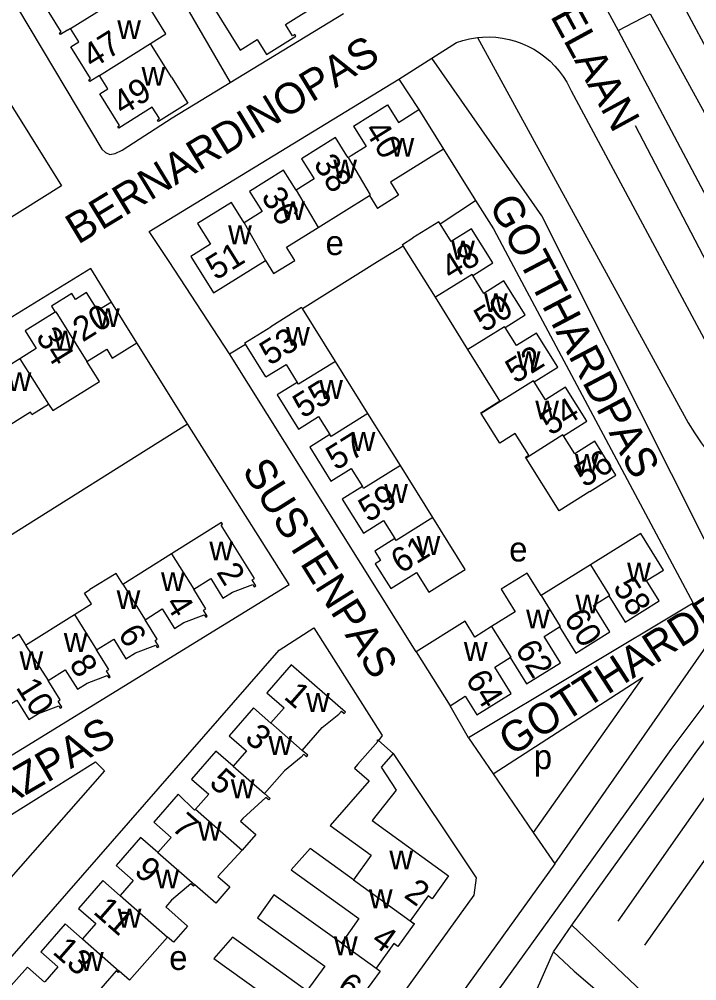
# Model space of a CAD drawing. Extents: x 158848 to 160613, y 385889 to 387762.
# Drawn here: x 159208.8 to 159319.2, y 386865.6 to 387022.2 of the extents above; entities that cross this region are included whole.
import ezdxf

# ---------------------------------------------------------------- set-up
doc = ezdxf.new("R2010")
doc.units = 0
for name, color, linetype in [('BLT_Basislijn', 7, 'Continuous'), ('BLT_Bebouwing', 7, 'Continuous'), ('BLT_Centroide', 7, 'Continuous'), ('BLT_Huisnummer', 7, 'Continuous'), ('BLT_Huisnummer_ tussenligend', 7, 'Continuous'), ('BLT_Onderverdeling_panden', 7, 'Continuous'), ('BLT_Straatnaam', 7, 'Continuous')]:
    doc.layers.add(name, color=color, linetype=linetype)

msp = doc.modelspace()

# ---------------------------------------------------------------- linework, layer by layer
at = {"layer": 'BLT_Basislijn'}
for p, q in [((159169.08, 387139.45), (159243.17, 387011.94)), ((159332.92, 386994.75), (159255.77, 387139.62)), ((159303.99, 387024.92), (159306.4, 387020.4)), ((159243.17, 387011.94), (159261.66, 387023.2)), ((159306.4, 387020.4), (159321.81, 386991.43)), ((159276.05, 387015.9), (159280.06, 387018.45)), ((159283.47, 387019.26), (159317.82, 386956.49)), ((159270.65, 387012.47), (159276.05, 387015.9)), ((159230, 386987.67), (159270.65, 387012.47)), ((159270.65, 387012.47), (159273.93, 387007.51)), ((159298.76, 387010.57), (159327.13, 386957.61)), ((159309.19, 387004.92), (159331.36, 386962.4)), ((159277.97, 387001.09), (159283.15, 386992.73)), ((159277.42, 386988.9), (159283.15, 386992.73)), ((159233.22, 386982.75), (159230, 386987.67)), ((159267.17, 386982.75), (159271.36, 386985.34)), ((159243.08, 386967.71), (159233.22, 386982.75)), ((159254.94, 386975.12), (159267.17, 386982.75)), ((159223.81, 386976.15), (159220.45, 386981.6)), ((159236.2, 386956.34), (159227.95, 386969.49)), ((159243.08, 386967.71), (159245.65, 386969.32)), ((159273.52, 386919.16), (159243.08, 386967.71)), ((159160.9, 386909.02), (159236.2, 386956.34)), ((159296.07, 386884.6), (159325.68, 386927.08)), ((159286.03, 386899.29), (159310.46, 386915.04)), ((159310.46, 386915.04), (159292.57, 386889.73)), ((159306.42, 386875.27), (159333.13, 386913.44)), ((159282.03, 386905.15), (159279.02, 386910.38)), ((159282.03, 386905.15), (159286.03, 386899.29)), ((159286.03, 386899.29), (159292.57, 386889.73)), ((159292.57, 386889.73), (159296.07, 386884.6)), ((159296.07, 386884.6), (159293.14, 386880.53)), ((159293.14, 386880.53), (159270.22, 386848.72)), ((159295.86, 386870.3), (159298.87, 386874.61)), ((159299.26, 386867.13), (159295.86, 386870.3))]:
    msp.add_line(p, q, dxfattribs=at)
for points in [[(159145.06, 387124.74), (159208.51, 387024.1), (159222.28, 387001.08), (159222.83, 387000.51), (159223.59, 387000.22), (159224.44, 387000.38), (159225.59, 387000.9), (159233.73, 387006.19), (159243.17, 387011.94)], [(159195.05, 387028.15), (159215.7, 386995.08), (159195.96, 386982.75)], [(159306.4, 387020.4), (159311.62, 387023.13), (159339.73, 386971.98)], [(159280.06, 387018.45), (159281.1, 387018.79), (159282.16, 387019.05), (159283.47, 387019.26)], [(159283.47, 387019.26), (159284.32, 387019.34), (159285.41, 387019.36), (159286.5, 387019.31), (159287.58, 387019.17), (159288.65, 387018.96), (159289.7, 387018.67), (159290.73, 387018.3), (159291.72, 387017.86), (159292.68, 387017.34), (159293.6, 387016.76), (159294.48, 387016.11), (159295.31, 387015.4), (159296.08, 387014.62), (159296.79, 387013.8), (159297.44, 387012.92), (159298.03, 387012), (159298.76, 387010.57)], [(159325.68, 386927.08), (159293.98, 386990.2), (159276.05, 387015.9)], [(159283.15, 386992.73), (159286.1, 386988.08), (159288.94, 386982.75)], [(159288.94, 386982.75), (159318.62, 386927.1), (159282.03, 386905.15)], [(159220.45, 386981.6), (159144.84, 386935.16), (159160.9, 386909.02)], [(159176.65, 386883.38), (159252.82, 386930.16), (159236.2, 386956.34)], [(159317.82, 386956.49), (159318.84, 386954.84), (159319.93, 386953.24), (159321.08, 386951.68), (159322.3, 386950.18), (159323.58, 386948.72), (159324.92, 386947.32), (159326.32, 386945.97), (159327.76, 386944.68), (159329.27, 386943.46), (159330.82, 386942.29), (159332.41, 386941.19), (159333.9, 386940.26)], [(159298.87, 386874.61), (159318.95, 386902.62), (159324.3, 386909.78), (159335.81, 386922.28), (159348.89, 386933.11)], [(159194.56, 386854.66), (159251.14, 386919.42), (159256.83, 386923.09), (159267.95, 386905.52), (159267.38, 386904.72)], [(159296.26, 386877.04), (159309.87, 386896.01), (159315.07, 386903.25), (159322.05, 386912.59), (159324, 386914.92)], [(159269.77, 386902.62), (159283.29, 386882.36), (159282.88, 386879.51), (159247.88, 386831.04), (159239.74, 386817.6), (159233.63, 386805.78), (159231.19, 386803.34), (159228.75, 386802.93), (159225.9, 386804.56), (159224.01, 386807.98)], [(159181.14, 386876.17), (159221.23, 386901.24), (159222.71, 386899.76), (159189.75, 386862.37)], [(159310.74, 386871.38), (159328.79, 386896.94), (159324.05, 386900.29)], [(159232.18, 386773.77), (159236.4, 386782.61), (159244.66, 386799.9), (159250.23, 386811.52), (159258.13, 386823.58), (159262.54, 386830.82), (159270.01, 386841.29), (159276.78, 386849.92), (159287.2, 386864.43), (159296.26, 386877.04)], [(159298.87, 386874.61), (159310.39, 386863.7), (159326.68, 386851.17), (159348.15, 386836.42)], [(159236.36, 386774.31), (159246.85, 386796.39), (159252.57, 386807.55), (159258.95, 386818.35), (159263.91, 386825.88), (159269.12, 386833.23), (159279.51, 386842.29), (159289.96, 386856.88), (159295.86, 386870.3)], [(159299.26, 386867.13), (159310.16, 386857.78)]]:
    msp.add_lwpolyline(points, dxfattribs=at)
at = {"layer": 'BLT_Bebouwing'}
for p, q in [((159217.13, 387020.74), (159216.66, 387020.45)), ((159217.14, 387020.71), (159217.13, 387020.74)), ((159233.63, 387012.81), (159230.2, 387018.29)), ((159262.41, 386999.69), (159262.22, 387000)), ((159262.9, 387000), (159262.41, 386999.69)), ((159257.54, 386988.32), (159265.88, 386993.52)), ((159265.88, 386993.52), (159267.2, 386991.41)), ((159276.62, 386976.93), (159271.36, 386985.34)), ((159281.94, 386968.43), (159276.62, 386976.93)), ((159260.32, 386966.5), (159254.94, 386975.12)), ((159249.01, 386963.95), (159245.65, 386969.32)), ((159265.62, 386958.02), (159260.32, 386966.5)), ((159210.86, 386957.84), (159213.57, 386959.52)), ((159270.92, 386949.54), (159265.62, 386958.02)), ((159276.22, 386941.06), (159270.92, 386949.54)), ((159233.63, 386935.12), (159225.68, 386930.16)), ((159301.91, 386933.34), (159293.85, 386928.32)), ((159225.68, 386930.16), (159225.67, 386930.18)), ((159289.65, 386925.69), (159285.79, 386923.29)), ((159209.84, 386920.26), (159217.8, 386925.25)), ((159209.83, 386920.29), (159209.84, 386920.26)), ((159273.52, 386919.16), (159279.02, 386910.38)), ((159249.82, 386907.59), (159249.8, 386907.56)), ((159267.25, 386904.84), (159267.38, 386904.72)), ((159267.38, 386904.72), (159269.77, 386902.62)), ((159243.68, 386900.55), (159243.65, 386900.52)), ((159231.39, 386886.49), (159231.37, 386886.46)), ((159225.25, 386879.45), (159225.23, 386879.43)), ((159272.53, 386875.35), (159273.18, 386874.89)), ((159273.18, 386874.89), (159273.15, 386874.84)), ((159219.1, 386872.42), (159219.08, 386872.39))]:
    msp.add_line(p, q, dxfattribs=at)
for points in [[(159243.66, 387027.03), (159242.84, 387026.52), (159243, 387026.25), (159240.22, 387024.51), (159244.79, 387017.2), (159247.57, 387018.94), (159249.1, 387016.49), (159253.86, 387019.47), (159253.7, 387019.74), (159253.36, 387019.53), (159252.21, 387021.39), (159257.66, 387024.79), (159257.49, 387025.06), (159257.21, 387024.89), (159253.99, 387030.04), (159252.65, 387029.22), (159251.29, 387031.43), (159253.44, 387032.76), (159253.27, 387033.03), (159252.99, 387032.86)], [(159216.66, 387020.45), (159215.52, 387019.74), (159215.36, 387020.02), (159215.63, 387020.19), (159212.4, 387025.36), (159213.71, 387026.17), (159212.36, 387028.34)], [(159230.2, 387018.29), (159232.7, 387019.85), (159229.33, 387025.31), (159226.79, 387023.74), (159225.45, 387025.89)], [(159221.88, 387013.1), (159220.29, 387012.12), (159220.12, 387012.39), (159220.39, 387012.56), (159217.18, 387017.72), (159218.5, 387018.54), (159217.14, 387020.71)], [(159233.63, 387012.81), (159236.28, 387008.57), (159231.49, 387005.57), (159231.32, 387005.84), (159231.65, 387006.05), (159230.49, 387007.9), (159225.05, 387004.49), (159224.88, 387004.77), (159225.15, 387004.93), (159221.94, 387010.1), (159223.24, 387010.91), (159221.88, 387013.1)], [(159263.3, 387004.82), (159268.83, 387008.29), (159270.62, 387005.44), (159273.93, 387007.51)], [(159273.93, 387007.51), (159277.97, 387001.09)], [(159263.3, 387004.82), (159265.36, 387001.53), (159262.9, 387000)], [(159262.22, 387000), (159260.36, 387002.98), (159254.81, 386999.51)], [(159277.97, 387001.09), (159269.31, 386995.68), (159270.63, 386993.55)], [(159254.81, 386999.51), (159256.86, 386996.22), (159253.93, 386994.39)], [(159253.93, 386994.39), (159251.88, 386997.67), (159246.33, 386994.2)], [(159246.33, 386994.2), (159248.39, 386990.92), (159245.45, 386989.08)], [(159270.63, 386993.55), (159267.2, 386991.41)], [(159245.45, 386989.08), (159243.4, 386992.37), (159237.85, 386988.96)], [(159237.85, 386988.96), (159239.97, 386985.57), (159236.76, 386983.56), (159240.45, 386977.65), (159248.93, 386982.94)], [(159277.42, 386988.9), (159277.2, 386989.25), (159272.96, 386986.6)], [(159282.52, 386988.09), (159279.21, 386986.03), (159277.42, 386988.9)], [(159253.69, 386982.95), (159252.36, 386985.08), (159257.54, 386988.32)], [(159282.71, 386980.49), (159285.99, 386982.54), (159282.52, 386988.09)], [(159271.36, 386985.34), (159271.24, 386985.52), (159272.96, 386986.6)], [(159248.93, 386982.94), (159250.26, 386980.81), (159253.69, 386982.95)], [(159287.8, 386979.61), (159284.53, 386977.57), (159282.71, 386980.49)], [(159287.99, 386972.01), (159291.27, 386974.06), (159287.8, 386979.61)], [(159219.76, 386977.72), (159217.95, 386976.59), (159217.35, 386977.55), (159214.03, 386975.47), (159214.63, 386974.5)], [(159223.81, 386976.15), (159221.6, 386974.77), (159219.76, 386977.72)], [(159227.95, 386969.49), (159223.81, 386976.15)], [(159214.63, 386974.5), (159209.78, 386971.47), (159211.58, 386968.6), (159208.9, 386966.93)], [(159254.94, 386975.12), (159254.83, 386975.29), (159249.79, 386972.14)], [(159245.65, 386969.32), (159245.55, 386969.49), (159249.79, 386972.14)], [(159293.09, 386971.11), (159289.83, 386969.07), (159287.99, 386972.01)], [(159292.73, 386963.17), (159296.56, 386965.57), (159293.09, 386971.11)], [(159208.9, 386966.93), (159206.31, 386965.3), (159204.51, 386968.18), (159202.69, 386967.04), (159202.08, 386968), (159198.76, 386965.93), (159199.36, 386964.96)], [(159219.81, 386966.45), (159223.05, 386968.48), (159223.96, 386967.01), (159227.95, 386969.49)], [(159284.1, 386957.99), (159284.02, 386958.12), (159287.15, 386960.09), (159281.94, 386968.43)], [(159213.57, 386959.52), (159214.27, 386958.48), (159221.86, 386963.21), (159219.81, 386966.45)], [(159249.01, 386963.95), (159252.28, 386965.99), (159254.11, 386963.06)], [(159254.11, 386963.06), (159250.84, 386961.02), (159254.31, 386955.47)], [(159297.84, 386962.28), (159294.56, 386960.23), (159292.73, 386963.17)], [(159297.49, 386954.36), (159301.3, 386956.75), (159297.84, 386962.28)], [(159210.86, 386957.84), (159210.63, 386958.2), (159205.69, 386955.12), (159204.59, 386956.9)], [(159254.31, 386955.47), (159257.59, 386957.52), (159259.42, 386954.58)], [(159291.4, 386950.74), (159291.31, 386950.88), (159291.86, 386951.22), (159289.65, 386954.76), (159287.12, 386953.17), (159284.1, 386957.99)], [(159259.42, 386954.58), (159256.14, 386952.53), (159259.61, 386946.99)], [(159302.59, 386953.47), (159299.33, 386951.42), (159297.49, 386954.36)], [(159301.82, 386945.28), (159306.06, 386947.93), (159302.59, 386953.47)], [(159301.82, 386945.28), (159296.78, 386942.13), (159291.4, 386950.74)], [(159259.61, 386946.99), (159262.89, 386949.04), (159264.72, 386946.11)], [(159264.72, 386946.11), (159261.44, 386944.06), (159264.91, 386938.51)], [(159237.23, 386929.36), (159240.01, 386931.1), (159242, 386927.93), (159243.57, 386928.9), (159246.89, 386930.12), (159247.11, 386929.75), (159247.37, 386929.91), (159246.76, 386930.89), (159247.12, 386931.11), (159241.7, 386939.8), (159241.95, 386939.96), (159241.79, 386940.22), (159233.63, 386935.12)], [(159264.91, 386938.51), (159268.19, 386940.55), (159270.02, 386937.62)], [(159279.81, 386931.54), (159281.5, 386932.6), (159276.22, 386941.06)], [(159313.12, 386927.46), (159311.06, 386930.78), (159313.83, 386932.5), (159310.11, 386938.46), (159301.91, 386933.34)], [(159270.02, 386937.62), (159266.74, 386935.57), (159267.69, 386934.06), (159266.83, 386933.52), (159269.36, 386929.51), (159270.22, 386930.03)], [(159225.67, 386930.18), (159224.57, 386931.94), (159220.32, 386929.3)], [(159270.22, 386930.03), (159273.56, 386932.12), (159275.57, 386928.9), (159279.81, 386931.54)], [(159293.85, 386928.32), (159291.57, 386931.98), (159287.37, 386929.36), (159289.65, 386925.69)], [(159217.8, 386925.25), (159220.55, 386926.97), (159219.43, 386928.75), (159220.32, 386929.3)], [(159229.31, 386924.4), (159232.1, 386926.15), (159234.09, 386922.98), (159235.65, 386923.97), (159238.96, 386925.21), (159239.2, 386924.84), (159239.45, 386925), (159238.85, 386925.96), (159239.21, 386926.19), (159237.23, 386929.36)], [(159305.07, 386922.42), (159302.4, 386926.71), (159304.91, 386928.27)], [(159304.91, 386928.27), (159307.58, 386923.99), (159313.12, 386927.46)], [(159221.4, 386919.5), (159224.21, 386921.21), (159226.19, 386918.05), (159227.74, 386919.02), (159231.04, 386920.26), (159231.28, 386919.88), (159231.54, 386920.03), (159230.93, 386921.01), (159231.29, 386921.24), (159229.31, 386924.4)], [(159285.79, 386923.29), (159283.06, 386921.58), (159281.46, 386924.14), (159273.52, 386919.16)], [(159297.01, 386917.39), (159294.34, 386921.68), (159296.84, 386923.24)], [(159296.84, 386923.24), (159299.51, 386918.95), (159305.07, 386922.42)], [(159201.91, 386915.31), (159200.8, 386917.09), (159208.73, 386922.04), (159209.83, 386920.29)], [(159213.5, 386914.51), (159216.3, 386916.26), (159218.28, 386913.09), (159219.85, 386914.07), (159223.15, 386915.3), (159223.38, 386914.93), (159223.64, 386915.09), (159223.03, 386916.06), (159223.4, 386916.3), (159221.4, 386919.5)], [(159288.96, 386912.37), (159286.29, 386916.65), (159288.8, 386918.22)], [(159288.8, 386918.22), (159291.47, 386913.94), (159297.01, 386917.39)], [(159254.92, 386903.11), (159258.19, 386906.84), (159260.9, 386909.03), (159261.32, 386909.49), (159261.75, 386909.1), (159261.96, 386909.33), (159253.12, 386917.06), (159249.14, 386912.51), (159251.96, 386910.05), (159249.82, 386907.59)], [(159205.56, 386909.61), (159208.39, 386911.31), (159210.37, 386908.14), (159211.93, 386909.12), (159215.24, 386910.36), (159215.47, 386909.98), (159215.73, 386910.14), (159215.12, 386911.12), (159215.48, 386911.34), (159213.5, 386914.51)], [(159279.02, 386910.38), (159281.5, 386911.93)], [(159281.5, 386911.93), (159283.4, 386908.91), (159288.96, 386912.37)], [(159249.8, 386907.56), (159246.98, 386910.02), (159243.01, 386905.47), (159245.82, 386903.01), (159243.68, 386900.55)], [(159263.94, 386900.81), (159267.24, 386904.56), (159267.11, 386904.68), (159267.25, 386904.84)], [(159243.65, 386900.52), (159240.84, 386902.98), (159236.86, 386898.44), (159239.68, 386895.98), (159237.54, 386893.52)], [(159255.62, 386902.08), (159255.16, 386902.47), (159254.75, 386901.99), (159252.04, 386899.8), (159248.79, 386896.06)], [(159255.62, 386902.08), (159255.83, 386902.32), (159254.92, 386903.11)], [(159269.77, 386902.62), (159267.77, 386900.35), (159270.22, 386896.63), (159266.31, 386891.68), (159278.78, 386882.65), (159276.09, 386878.93), (159275.44, 386879.39), (159272.53, 386875.35)], [(159263.94, 386900.81), (159263.43, 386900.23), (159265.81, 386898.13), (159259.47, 386890.86), (159266.18, 386886.03), (159263.29, 386882.02)], [(159237.54, 386893.52), (159237.39, 386893.36), (159234.69, 386895.95), (159230.72, 386891.4), (159233.54, 386888.94), (159231.39, 386886.49)], [(159248.79, 386896.06), (159249.69, 386895.28), (159249.48, 386895.03), (159249.01, 386895.43), (159245.23, 386891.99), (159244.88, 386891.59), (159247.38, 386889.38), (159245.14, 386886.86)], [(159231.37, 386886.46), (159228.55, 386888.92), (159224.57, 386884.36), (159227.39, 386881.9), (159225.25, 386879.45)], [(159245.14, 386886.86), (159241.15, 386882.57), (159243.13, 386880.86), (159240.84, 386878.22), (159237.41, 386881.19)], [(159263.29, 386882.02), (159256.2, 386887.12), (159253.13, 386883.62), (159264.16, 386875.71), (159261.3, 386871.69)], [(159225.23, 386879.43), (159222.42, 386881.89), (159218.44, 386877.34), (159221.26, 386874.88), (159219.1, 386872.42)], [(159237.41, 386881.19), (159237.2, 386880.96), (159236.74, 386881.36), (159233.62, 386878.69), (159232.67, 386877.6), (159236.23, 386874.48), (159233.93, 386871.84), (159232.95, 386872.7)], [(159261.3, 386871.69), (159250.31, 386879.58), (159247.61, 386875.83), (159258.58, 386867.95), (159255.69, 386863.93)], [(159219.08, 386872.39), (159216.26, 386874.85), (159212.3, 386870.31), (159215.11, 386867.85), (159212.96, 386865.38)], [(159273.15, 386874.84), (159270.49, 386871.16), (159269.84, 386871.62), (159266.96, 386867.62)], [(159232.95, 386872.7), (159226.79, 386865.67), (159225.11, 386867.13)], [(159255.69, 386863.93), (159243.56, 386872.67), (159240.52, 386869.19), (159253.02, 386860.24), (159250.12, 386856.2)], [(159212.94, 386865.35), (159210.12, 386867.81), (159206.14, 386863.26), (159208.96, 386860.8), (159206.82, 386858.35)], [(159225.11, 386867.13), (159224.9, 386866.89), (159224.57, 386867.18), (159221.01, 386863.08), (159223.95, 386860.51), (159221.6, 386857.82), (159218.99, 386860.1)], [(159266.96, 386867.62), (159267.61, 386867.15), (159264.92, 386863.42), (159264.27, 386863.89), (159261.36, 386859.85)]]:
    msp.add_lwpolyline(points, dxfattribs=at)
at = {"layer": 'BLT_Onderverdeling_panden'}
for p, q in [((159217.14, 387020.71), (159225.45, 387025.89)), ((159216.66, 387020.45), (159217.14, 387020.71)), ((159221.88, 387013.1), (159230.2, 387018.29)), ((159253.93, 386994.39), (159257.54, 386988.32)), ((159245.45, 386989.08), (159248.93, 386982.94)), ((159208.9, 386966.93), (159213.57, 386959.52)), ((159233.63, 386935.12), (159237.23, 386929.36)), ((159225.67, 386930.18), (159229.31, 386924.4)), ((159217.8, 386925.25), (159221.4, 386919.5)), ((159209.84, 386920.26), (159213.5, 386914.51)), ((159249.82, 386907.59), (159254.92, 386903.11)), ((159243.68, 386900.55), (159248.79, 386896.06)), ((159237.54, 386893.52), (159245.14, 386886.86)), ((159231.39, 386886.49), (159237.41, 386881.19)), ((159263.29, 386882.02), (159272.53, 386875.35)), ((159225.25, 386879.45), (159232.95, 386872.7)), ((159272.53, 386875.35), (159273.15, 386874.84)), ((159219.1, 386872.42), (159225.11, 386867.13)), ((159261.3, 386871.69), (159266.96, 386867.62))]:
    msp.add_line(p, q, dxfattribs=at)
for points in [[(159262.41, 386999.69), (159266.02, 386993.62), (159265.88, 386993.52)], [(159282.71, 386980.49), (159282.62, 386980.63), (159276.62, 386976.93)], [(159214.63, 386974.5), (159214.74, 386974.57), (159219.81, 386966.45)], [(159287.99, 386972.01), (159287.91, 386972.14), (159281.94, 386968.43)], [(159260.32, 386966.5), (159254.32, 386962.76), (159254.11, 386963.06)], [(159292.73, 386963.17), (159292.64, 386963.31), (159284.1, 386957.99)], [(159265.62, 386958.02), (159259.62, 386954.28), (159259.42, 386954.58)], [(159297.49, 386954.36), (159297.41, 386954.5), (159291.4, 386950.74)], [(159270.92, 386949.54), (159264.93, 386945.8), (159264.72, 386946.11)], [(159276.22, 386941.06), (159270.23, 386937.32), (159270.02, 386937.62)], [(159301.91, 386933.34), (159305.03, 386928.35), (159304.91, 386928.27)], [(159293.85, 386928.32), (159296.97, 386923.32), (159296.84, 386923.24)], [(159285.79, 386923.29), (159288.92, 386918.29), (159288.8, 386918.22)]]:
    msp.add_lwpolyline(points, dxfattribs=at)

# ---------------------------------------------------------------- texts
at = {"layer": 'BLT_Centroide'}
for s, p in [('w', (159224.77, 387019)), ('w', (159228.73, 387011.41)), ('w', (159269.32, 386999.84)), ('w', (159259.98, 386996.3)), ('w', (159251.5, 386989.52)), ('w', (159242.84, 386985.59)), ('e', (159258.73, 386983.82)), ('w', (159279.2, 386983.09)), ('w', (159284.55, 386974.53)), ('w', (159221.32, 386972.09)), ('w', (159214.36, 386968.42)), ('w', (159252.3, 386969.03)), ('w', (159289.9, 386965.06)), ('w', (159206.91, 386961.66)), ('w', (159257.69, 386960.38)), ('w', (159292.91, 386957.03)), ('w', (159262.98, 386951.91)), ('w', (159299.38, 386948.31)), ('w', (159268.28, 386943.44)), ('w', (159239.78, 386934.06)), ('w', (159273.56, 386934.97)), ('e', (159288.66, 386933.89)), ('w', (159307.88, 386930.61)), ('w', (159231.9, 386929.06)), ('w', (159224.67, 386926.12)), ('w', (159299.47, 386925.42)), ('w', (159291.41, 386922.97)), ('w', (159216.06, 386919.16)), ('w', (159281.27, 386917.67)), ('w', (159208.84, 386916.2)), ('w', (159255.55, 386909.38)), ('w', (159249.42, 386902.36)), ('p', (159292.67, 386900.05)), ('w', (159243.28, 386895.3)), ('w', (159237.92, 386888.41)), ('w', (159269.12, 386883.72)), ('w', (159231, 386880.61)), ('w', (159265.79, 386877.38)), ('w', (159224.84, 386874.22)), ('w', (159260.09, 386869.72)), ('w', (159218.7, 386867.17)), ('e', (159233.24, 386867.33))]:
    msp.add_text(s, height=4, dxfattribs=at).set_placement(p)
at = {"layer": 'BLT_Huisnummer'}
for s, rotation, p in [('49', 31.9596, (159225.64, 387006.45)), ('40', 301.9975, (159264.93, 387004.19)), ('36', 301.9975, (159248.13, 386993.36)), ('51', 31.9844, (159240.84, 386979.62)), ('48', 31.9861, (159279.16, 386979.59)), ('20', 31.9847, (159219.14, 386969.56)), ('34', 301.9589, (159211.39, 386970.53)), ('53', 31.9843, (159249.61, 386965.71)), ('52', 31.9861, (159289.67, 386962.78)), ('57', 31.9843, (159260.42, 386948.63)), ('56', 31.9861, (159300.92, 386945.84)), ('61', 31.9843, (159271, 386931.81)), ('2', 301.9893, (159240.84, 386932.15)), ('58', 301.9818, (159305.48, 386929.72)), ('6', 301.9893, (159224.79, 386922.1)), ('10', 301.9893, (159208.16, 386913.38)), ('64', 301.9818, (159281.42, 386914.71)), ('1', 318.7689, (159251.75, 386911.67)), ('5', 318.7689, (159239.57, 386897.57)), ('9', 318.7689, (159227.35, 386883.18)), ('2', 324.1578, (159271.33, 386879.28)), ('6', 324.1578, (159260.31, 386864.01))]:
    msp.add_text(s, height=4, rotation=rotation, dxfattribs=at).set_placement(p)
at = {"layer": 'BLT_Huisnummer_ tussenligend'}
for s, rotation, p in [('47', 31.9596, (159220.71, 387014.09)), ('38', 301.9975, (159256.66, 386998.7)), ('50', 31.9861, (159284.56, 386971.12)), ('55', 31.9843, (159255.02, 386957.11)), ('54', 31.9861, (159295.38, 386954.31)), ('59', 31.9843, (159265.71, 386940.17)), ('4', 301.9893, (159232.49, 386927.01)), ('60', 301.9818, (159297.46, 386924.64)), ('62', 301.9818, (159289.51, 386919.6)), ('8', 301.9893, (159216.84, 386917.19)), ('3', 318.7689, (159245.37, 386904.83)), ('7', 318.7689, (159233.45, 386890.32)), ('11', 318.7689, (159220.69, 386876.63)), ('4', 324.1578, (159265.98, 386871.71)), ('13', 318.7689, (159214.05, 386870.11))]:
    msp.add_text(s, height=4, rotation=rotation, dxfattribs=at).set_placement(p)
at = {"layer": 'BLT_Straatnaam'}
for s, rotation, p in [('ESTAFETTELAAN', 298.6029, (159278.91, 387052.77)), ('BERNARDINOPAS', 31.3077, (159218.37, 386985.46)), ('GOTTHARDPAS', 297.7471, (159285.27, 386992.06)), ('SUSTENPAS', 302.0779, (159245.01, 386948.71)), ('GOTTHARDPAS', 32.756, (159289.07, 386902.06)), ('FORCLAZPAS', 30.174, (159186.33, 386882.08))]:
    msp.add_text(s, height=5, rotation=rotation, dxfattribs=at).set_placement(p)

doc.saveas('drawing.dxf')
